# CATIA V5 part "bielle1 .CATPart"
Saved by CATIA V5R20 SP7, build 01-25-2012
Part number: bielle1 
Publications: "droite_bielle_1", "droite_pivot_1_0", "droite_pivot_1_2_6"
Bounding box of the stored display mesh (mm): x 0 to 0.5, y 0 to 2.07, z 0 to 2.17
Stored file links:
  U:\IAO\bielle1 .CATPart
  U:\IAO\skl_brevet_iao.CATProduct
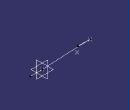
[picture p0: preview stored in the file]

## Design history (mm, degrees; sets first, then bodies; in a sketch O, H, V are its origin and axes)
Set1
  Point1 "point A": linked copy from another document
  Point2 "point B": linked copy from another document
  Point3 "point F": linked copy from another document
Set2
  Line1 "droite_bielle_1": type PtPt, FirstPoint Point1, SecondPoint Point2
  Line2 "droite_pivot_1_0": type Normal, RefPoint Point1, RefSkin yz-plane, Start 0, End 0.5
  Line3 "droite_pivot_1_2_6": type Normal, RefPoint Point2, RefSkin yz-plane, Start 0, End 0.5
Body1 (main body)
